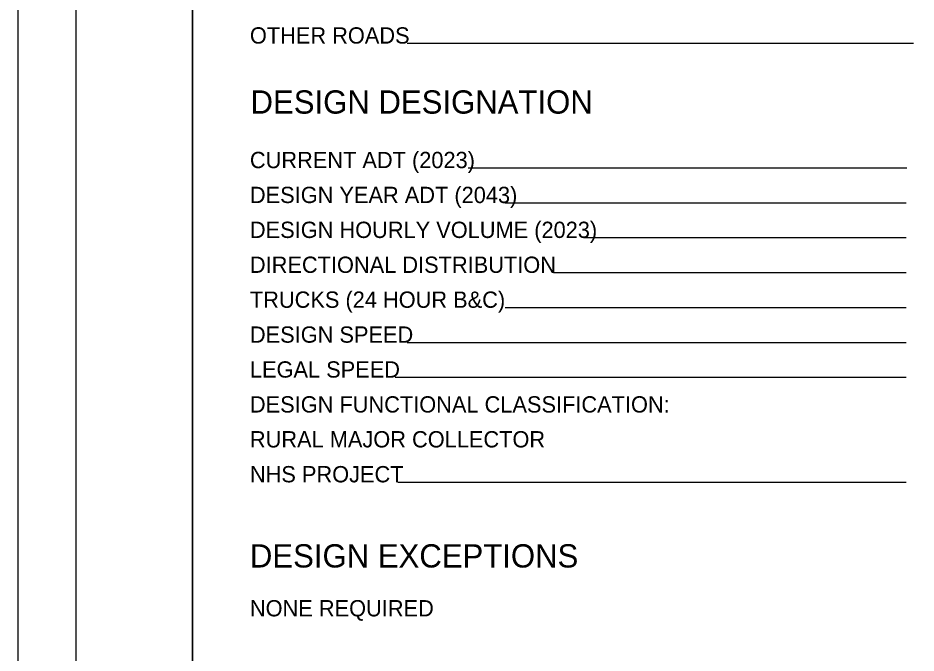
# Model space of a CAD drawing. Extents: x 0 to 34, y 0 to 22.
# Drawn here: x 0 to 7.72, y 5.64 to 11.1 of the extents above; entities that cross this region are included whole.
import ezdxf

# ---------------------------------------------------------------- set-up
doc = ezdxf.new("R2010")
doc.units = 0
for name, color, linetype in [('SH_Border', 7, 'Continuous'), ('SH_Cut_Line', 7, 'Continuous'), ('SH_Data', 7, 'Continuous'), ('SH_Text', 7, 'Continuous')]:
    doc.layers.add(name, color=color, linetype=linetype)

msp = doc.modelspace()

# ---------------------------------------------------------------- linework, layer by layer
at = {"layer": 'SH_Border'}
for points in [[(0.5, 21.5), (1.5, 21.5), (1.5, 0.5), (0.5, 0.5)], [(1.5, 21.5), (33.5, 21.5), (33.5, 0.5), (1.5, 0.5)]]:
    msp.add_lwpolyline(points, close=True, dxfattribs=at)
at = {"layer": 'SH_Cut_Line'}
msp.add_lwpolyline([(0, 0), (34, 0), (34, 22), (0, 22)], close=True, dxfattribs=at)
at = {"layer": 'SH_Data'}
for p, q in [((7.7, 10.8767), (3.3471, 10.8767)), ((7.6424, 9.8062), (3.871, 9.8062)), ((7.6368, 9.5062), (4.1885, 9.5062)), ((7.6368, 9.2062), (4.8723, 9.2062)), ((7.6368, 8.9062), (4.6037, 8.9062)), ((7.6368, 8.6062), (4.1885, 8.6062)), ((7.6368, 8.3062), (3.346, 8.3062)), ((7.6368, 8.0062), (3.2422, 8.0062)), ((7.6368, 7.1062), (3.2669, 7.1062))]:
    msp.add_line(p, q, dxfattribs=at)

# ---------------------------------------------------------------- texts
msp.add_text('DESIGN DESIGNATION', height=0.2, dxfattribs=at).set_placement((2, 10.2747))
at = {"layer": 'SH_Text'}
for s, height, p in [('OTHER ROADS', 0.14, (1.9944, 10.8767)), ('CURRENT ADT (2023)', 0.14, (1.9944, 9.8062)), ('DESIGN YEAR ADT (2043)', 0.14, (1.9944, 9.5062)), ('DESIGN HOURLY VOLUME (2023)', 0.14, (1.9944, 9.2062)), ('DIRECTIONAL DISTRIBUTION', 0.14, (1.9944, 8.9062)), ('TRUCKS (24 HOUR B&C)', 0.14, (1.9944, 8.6062)), ('DESIGN SPEED', 0.14, (1.9944, 8.3062)), ('LEGAL SPEED', 0.14, (1.9944, 8.0062)), ('DESIGN FUNCTIONAL CLASSIFICATION:', 0.14, (1.9944, 7.7062)), ('RURAL MAJOR COLLECTOR', 0.14, (1.9944, 7.4062)), ('NHS PROJECT', 0.14, (1.9944, 7.1062)), ('DESIGN EXCEPTIONS', 0.2, (1.9944, 6.3744)), ('NONE REQUIRED', 0.14, (1.9944, 5.9544))]:
    msp.add_text(s, height=height, dxfattribs=at).set_placement(p)

doc.saveas('drawing.dxf')
